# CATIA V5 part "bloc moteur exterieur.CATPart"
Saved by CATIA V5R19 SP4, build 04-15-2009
Part number: bloc moteur exterieur
Bounding box of the stored display mesh (mm): x 0 to 84.21, y -13.25 to 88.64, z -50.945 to 50.945
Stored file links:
  G:\EU_thinkMotion\CFAO_2010\MMS_groupe1\MMS_groupe1\A reprendre\OK\rdeneffle\bloc moteur exterieur.CATPart
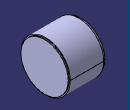
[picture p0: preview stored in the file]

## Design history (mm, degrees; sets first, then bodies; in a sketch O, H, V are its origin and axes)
Body1 (main body)
  Sketch1 on yz-plane, origin (0, 0, 0), H (0, 1, 0), V (0, 0, 1)
    circle A1 centre (37.6949, 0) radius 50.945
    point P1 (37.6949, 0)
    radius A1 = 50.945
    coincidence: P1 H
  Pad1: profile Sketch1, direction (1, 0, 0), length 84.21
  Sketch2 on end face of Pad1, origin (84.21, 0, 0), H (0, 1, 0), V (0, 0, 1)
    circle A1 centre (37.6949, 0) radius 48.73
    circle A2 centre (37.6949, 0) radius 50.945
    reference projected circle E1 centre (37.6949, 0) radius 50.945 from edge [face of Pad1 from Sketch1.A1 | end face of Pad1]
    reference projected circle E2 centre (37.6949, 0) radius 50.945 from edge [face of Pad1 from Sketch1.A1 | end face of Pad1]
    distance A2 A1 = 2.215
    coincidence: A2 E1
    concentricity: A1 E2
  Pocket1: profile Sketch2, direction (-1, 0, 0), length 2.215
  Sketch3 on start face of Pad1, origin (0, 0, 0), H (0, -1, 0), V (0, 0, 1)
    circle A1 centre (-37.6949, 0) radius 50.945
    circle A2 centre (-37.6949, 0) radius 48.695
    reference projected circle E1 centre (-37.6949, 0) radius 50.945 from edge [start face of Pad1 | face of Pad1 from Sketch1.A1]
    distance A2 A1 = 2.25
    coincidence: A1 E1
    concentricity: A2 A1
  Pocket2: profile Sketch3, direction (1, 0, 0), length 13.29
  Sketch4 on start face of Pad1, origin (0, 0, 0), H (0, -1, 0), V (0, 0, 1)
    circle A1 centre (-37.6949, 0) radius 48.695
    reference projected circle E1 centre (-37.6949, 0) radius 48.695 from edge [face of Pocket2 from Sketch3.A2 | start face of Pad1]
    circle A2 centre (-37.6949, 0) radius 39.835
    distance A2 A1 = 8.86
    coincidence: A1 E1
    concentricity: A1 A2
  Pocket3: profile Sketch4, direction (1, 0, 0), length 8.86
  Sketch5 on start face of Pad1, origin (0, 0, 0), H (0, -1, 0), V (0, 0, 1)
    circle A1 centre (-37.6949, 0) radius 28.76
    circle A2 centre (-37.6949, 0) radius 39.835
    reference projected circle E1 centre (-37.6949, 0) radius 39.835 from edge [face of Pocket3 from Sketch4.A2 | start face of Pad1]
    distance A1 A2 = 11.075
    coincidence: A2 E1
    concentricity: A1 A2
  Pocket4: profile Sketch5, direction (1, 0, 0), length 4.43
  Fillet1: radius 5, on edge [face of Pocket4 from Sketch5.A1 | start face of Pad1]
